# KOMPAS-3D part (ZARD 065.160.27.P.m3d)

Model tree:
1. Булева операция:1
2. Булева операция:2
3. Булева операция:3
4. Булева операция:4
5. Булева операция:5
6. Булева операция:6
7. Булева операция:7
8. Булева операция:8
9. Булева операция:9
10. Булева операция:10
11. Булева операция:11
12. Булева операция:12
13. Булева операция:13  (labels: C:\Program Files\ASCON\KOMPAS-3D V13\Sys\graphic.lyt)
